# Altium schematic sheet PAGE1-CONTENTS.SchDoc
size A3
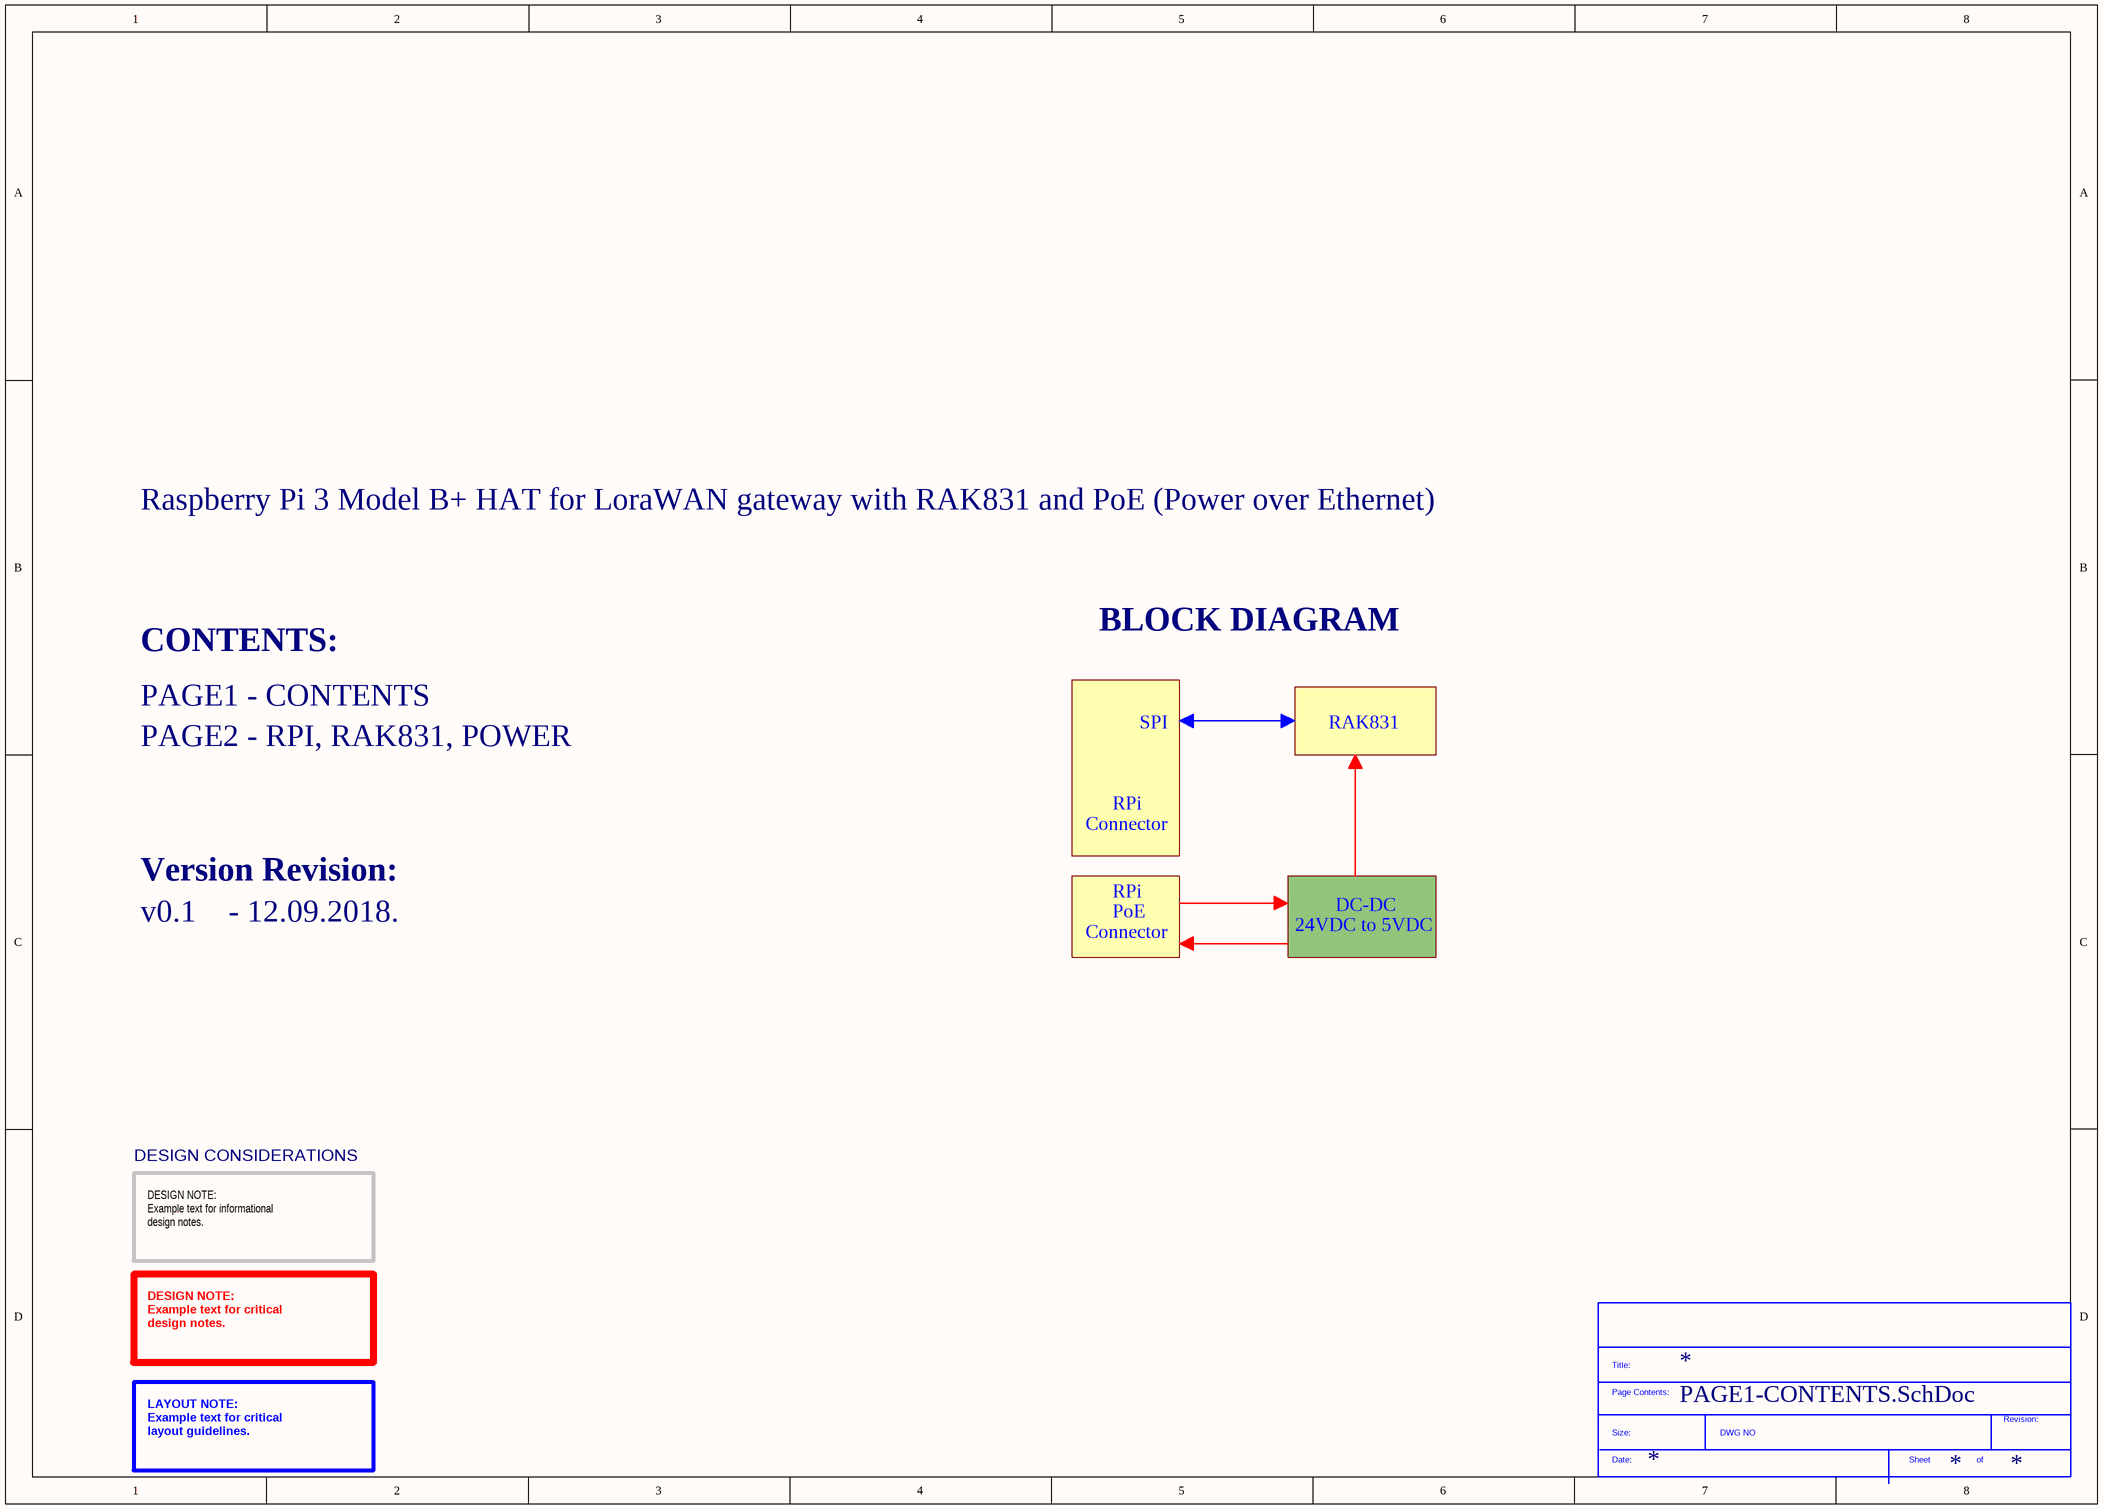
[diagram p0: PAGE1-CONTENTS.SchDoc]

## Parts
*?  SDTitleBlock  (value not drawn)  (graphical)

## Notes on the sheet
- Raspberry Pi 3 Model B+ HAT for LoraWAN gateway with RAK831 and PoE (Power over Ethernet)
- BLOCK DIAGRAM
- CONTENTS:
- PAGE1 - CONTENTS
- PAGE2 - RPI, RAK831, POWER
- SPI
- RAK831
- Connector
- RPi
- Version Revision:
- PoE
- DC-DC
- v0.1    - 12.09.2018.
- 24VDC to 5VDC
- DESIGN CONSIDERATIONS
- DESIGN NOTE:
  Example text for informational
  design notes.
- DESIGN NOTE:
  Example text for critical
  design notes.
- LAYOUT NOTE:
  Example text for critical
  layout guidelines.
